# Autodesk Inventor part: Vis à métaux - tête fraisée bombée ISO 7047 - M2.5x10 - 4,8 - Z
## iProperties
Author: Flavien MARTY
Shininess: 20.0
Angle Display Precision: 2
Document Length Units: 11269
Document Angle Units: 11283
Document Time Units: 11279
Document Mass Units: 11290
Document Length Units Precision: 3
Document Angle Units Precision: 2
Compacted: True
PropertySet Name: _Private Model Information
Created: 2002-05
Part Number: Vis à métaux - tête fraisée bombée ISO 7047 - M2.5x10 - 4,8 - Z
Material: Par défaut
Catalog Web Link: www.traceparts.com
Description: Vis à métaux - tête fraisée bombée ISO 7047 - M2.5x10 - 4,8 - Z
Document SubType Name: Modélisation
Designer: Flavien MARTY
Control State: 0
Master: False
Checked Out: False
PropertySet Name: Design Tracking Control
Density: 0.0
Volumn: 0.0
Area: 0.0
PropertySet Name: Model Information
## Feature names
1. Base1
